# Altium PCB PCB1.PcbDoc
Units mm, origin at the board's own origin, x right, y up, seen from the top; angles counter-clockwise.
Board outline 160 x 100 mm, 4 copper layers (Top Layer, Top inner, Bottom inner, Bottom Layer), stack 1.538 mm thick; 142 components, 85 nets, 480 pads, 109 vias.
Unrouted connection lines stored in the file: 1.
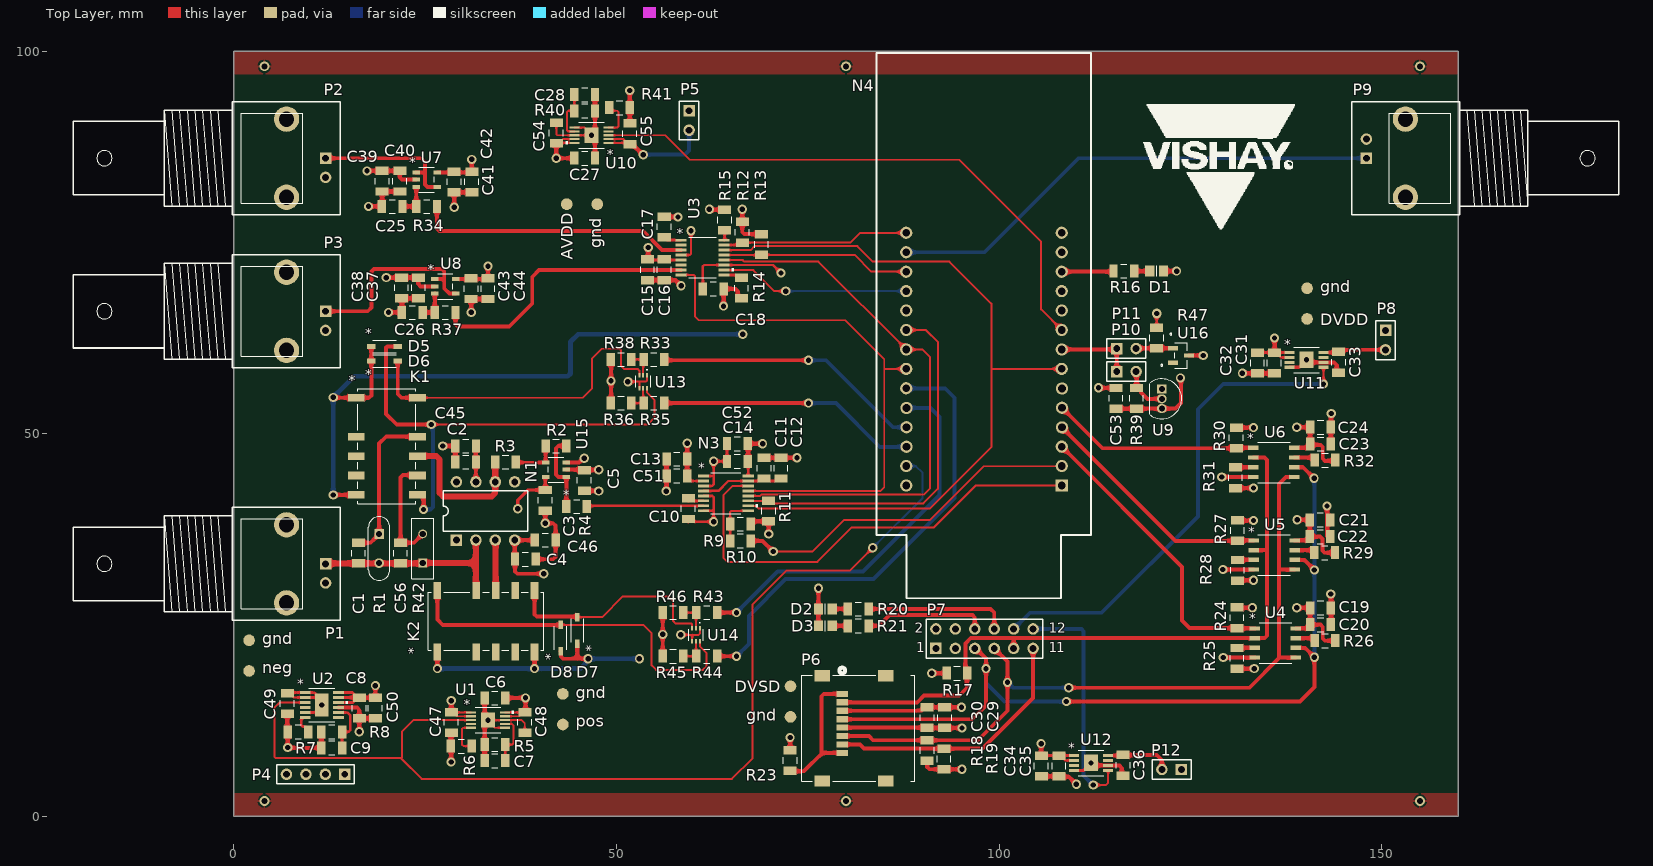
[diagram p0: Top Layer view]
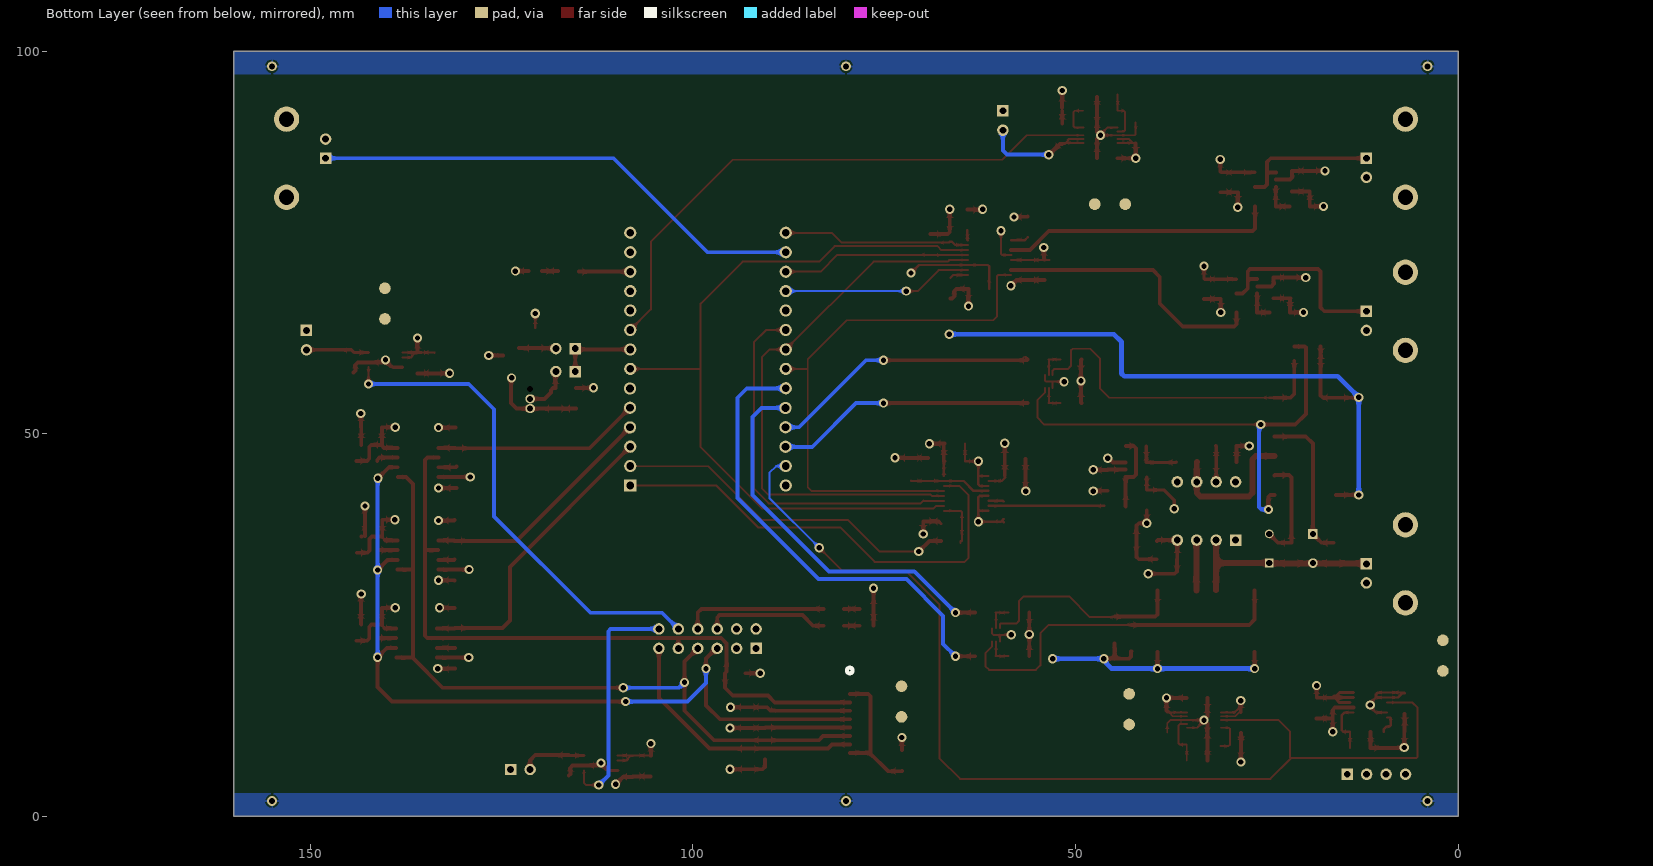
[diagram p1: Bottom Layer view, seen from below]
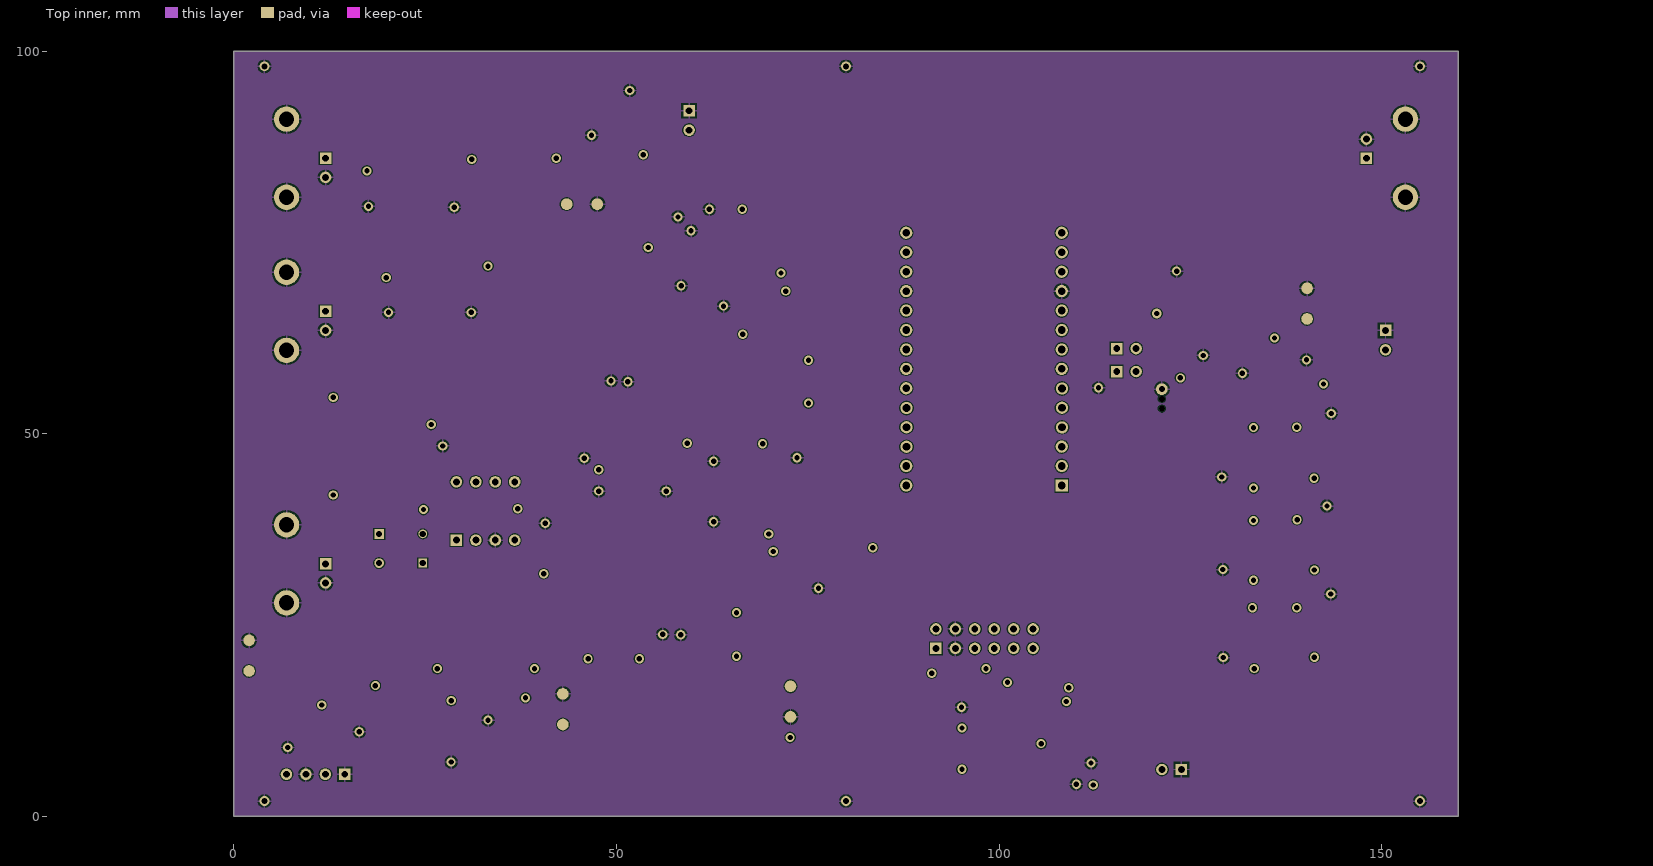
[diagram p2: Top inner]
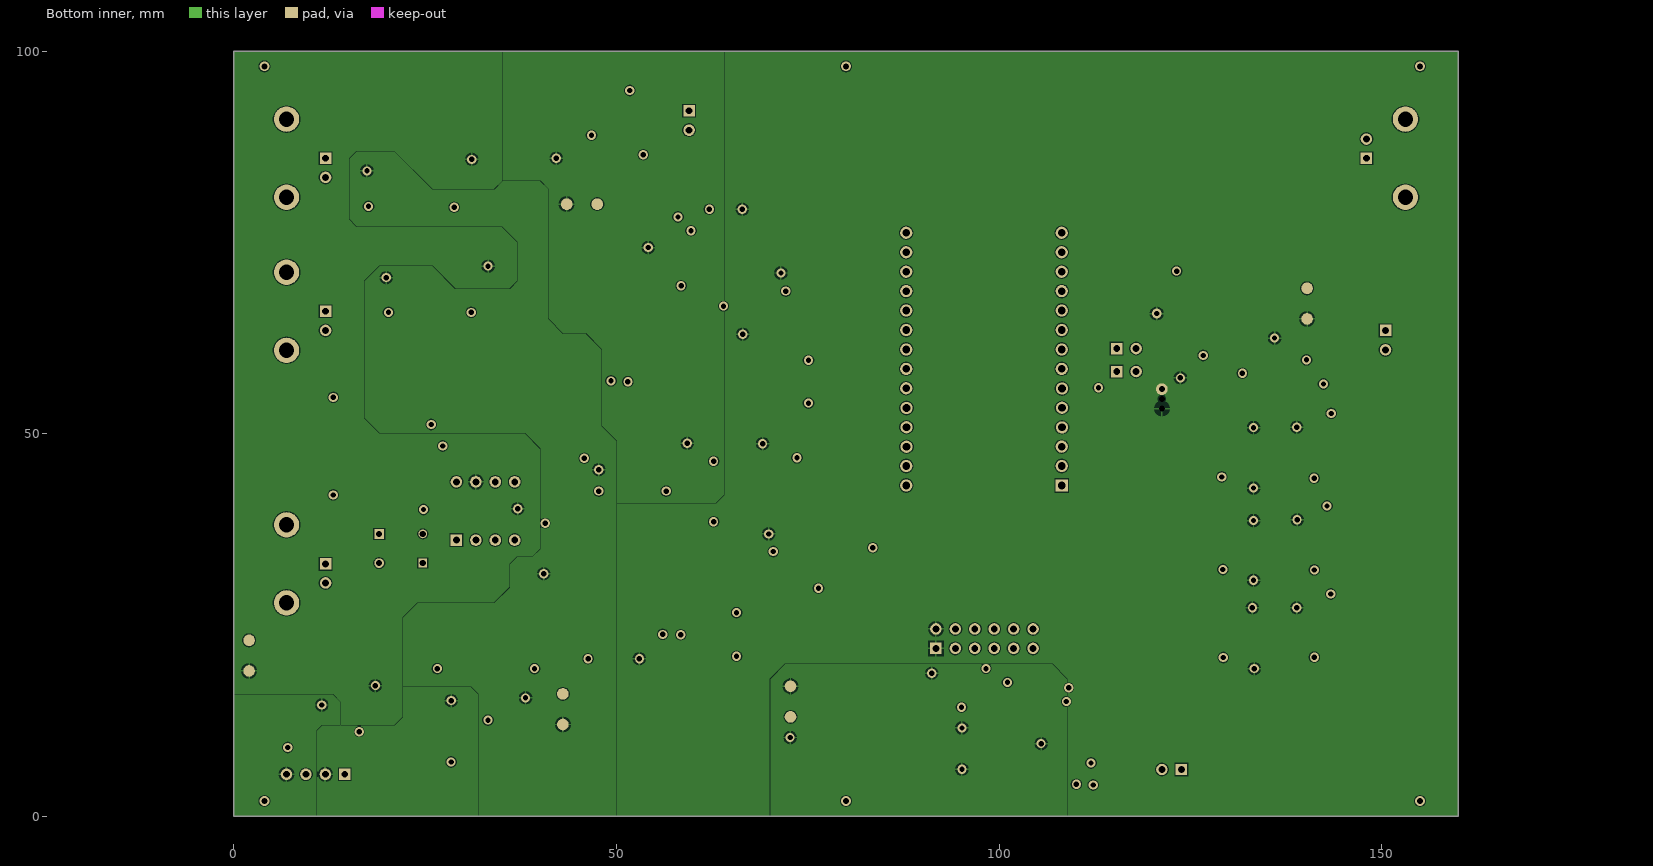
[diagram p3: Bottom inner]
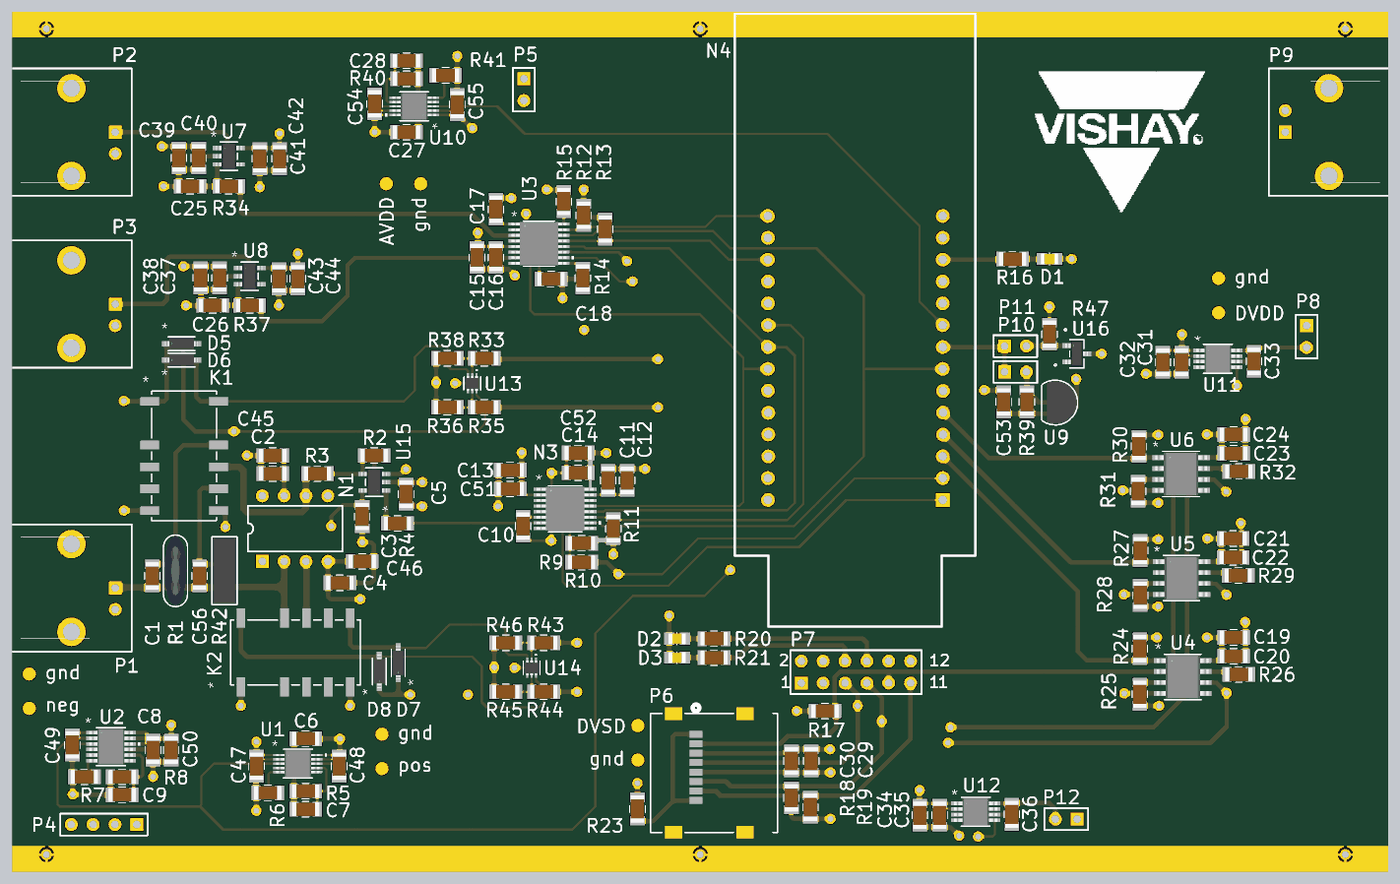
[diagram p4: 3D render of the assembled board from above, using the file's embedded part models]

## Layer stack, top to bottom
Top Solder: solder mask 0.0102, Solder Resist, Dk 3.5
Top Layer: signal copper 0.0356
Dielectric 4: prepreg 0.1524, PP-006, Dk 4.4
Top inner: signal copper 0.035
Dielectric 1: dielectric 1.0922, FR-4, Dk 4.8
Bottom inner: signal copper 0.035
Dielectric 5: prepreg 0.1524, PP-006, Dk 4.4
Bottom Layer: signal copper 0.0356
Bottom Solder: solder mask 0.0102, Solder Resist, Dk 3.5

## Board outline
0,0 160,0 160,100 0,100

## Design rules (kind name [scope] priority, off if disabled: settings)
Clearance [All] p1: gap=0.127 ignorepadtopadclearanceinfootprint=TRUE except(0.025: THPad-THPad)
MinimumSolderMaskSliver THT_21-0248A_Q3-1_MXM [HasFootprint('21-0248A_Q3-1_MXM')] p1: minsoldermaskwidth=0
MinimumSolderMaskSliver [All] p2: minsoldermaskwidth=0.127
PolygonConnect [All] p1: connectstyle=Relief reliefconductorwidth=0.254 reliefentries=4 polygonreliefangle="90 Angle" airgapwidth=0.254
RoutingVias [All] p1: holewidth=0.6 width=1.2 viastyle="Through Hole" minholewidth=0.3 minwidth=0.6 maxholewidth=1 maxwidth=2
SilkToSolderMaskClearance SilkToSolderMaskClearance_1 [HasFootprint('BNC_RA CON')] p1: minsilkscreentomaskgap=0 clearancetoexposedcopper=TRUE
SilkToSolderMaskClearance [IsPad] p2: minsilkscreentomaskgap=0.127 clearancetoexposedcopper=TRUE
SolderMaskExpansion [All] p1: expansion=0.102 istentingtop=FALSE
Width Source [InNet('M_source')] p1: maxlimit=2.54 minlimit=0.254 preferedwidth=0.762
Width Width_1 [All] p2: maxlimit=0.762 minlimit=0.254 preferedwidth=0.762
28 further rules are at their usual default settings.

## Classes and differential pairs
component class U_Cal: R33 R35 R36 R38 R43 R44 R45 R46 U13 U14
component class U_Digital_Psu: C31 C32 C33 C34 C35 C36 U11 U12
component class U_Analog_PSU_5: C27 C28 C54 R40 R41 U10
component class U_Temp_Sensors: C53 P10 P11 R39 R47 U9 U16
component class U_Source_TIA: C1 C2 C3 C4 C5 C45 C46 C56 D5 D6 D7 D8 K1 K2 N1 R1 R2 R3 R4 R42 U15
component class U_PSRAM_SPI: C19 C20 C21 C22 C23 C24 R24 R25 R26 R27 R28 R29 R30 R31 R32 U4 U5 U6
component class U_OPV_psu: C6 C7 C8 C9 C47 C48 C49 C50 R5 R6 R7 R8 U1 U2
component class U_DAC_Buffer_Filter: C25 C26 C37 C38 C39 C40 C41 C42 C43 C44 R34 R37 U7 U8
component class U_CortexM3_dev: C29 C30 D1 D2 D3 N4 P6 R16 R17 R18 R19 R20 R21 R23
component class U_ADC_8681: C10 C11 C12 C13 C14 C51 C52 N3 R9 R10 R11
component class U_AD_5689_DAC: C15 C16 C17 C18 R12 R13 R14 R15 U3
component class Top_Sheet: C55 P1 P2 P3 P4 P5 P8 P9 P12

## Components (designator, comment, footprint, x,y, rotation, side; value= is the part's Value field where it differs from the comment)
C1 "22pF" C1206-KUE 16.3,34.4 r90 top
C2 "100nF" C1206-KUE 30.3,46.3 r0 top
C3 "100nF" C1206-KUE 40.7,41.3 r90 top
C4 "100nF" C1206-KUE 38.1,33.6 r180 top
C5 "100nF" C1206-KUE 45.8,43.9 r90 top
C6 "10uF" C1206-KUE 34.123,15.477 r0 top
C7 "4.7uF" C1206-KUE 34.123,7.277 r0 top
C8 "10uF" C1206-KUE 16.4,14.149 r90 top
C9 "4.7uF" C1206-KUE 12.8,8.949 r0 top
C10 "10uF" C1206-KUE 59.4,40.2 r90 top
C11 "100nF" C1206-KUE 69.3,45.5 r270 top
C12 "10uF" C1206-KUE 71.5,45.5 r270 top
C13 "0.1uF" C1206-KUE 57.9,46.7 r0 top
C14 "0.1uF" C1206-KUE 65.8,46.4 r0 top
C15 "10uF" C1206-KUE 54.05,71.425 r90 top
C16 "0.1uF" C1206-KUE 56.25,71.425 r90 top
C17 "0.1uF" C1206-KUE 56.25,77.025 r270 top
C18 "0.1uF" C1206-KUE 62.65,68.925 r180 top
C19 "1uF" C1206-KUE 142,27.25 r180 top
C20 "100nF" C1206-KUE 142,25.05 r180 top
C21 "1uF" C1206-KUE 141.95,38.75 r180 top
C22 "100nF" C1206-KUE 141.95,36.55 r180 top
C23 "1uF" C1206-KUE 142,48.65 r180 top
C24 "100nF" C1206-KUE 142,50.85 r180 top
C25 "1uF" C1206-KUE 20.7,79.7 r0 top
C26 "1uF" C1206-KUE 23.324,65.85 r0 top
C27 "10uF" C1206-KUE 45.849,86 r180 top
C28 "4.7uF" C1206-KUE 45.849,94.3 r180 top
C29 "100nF" C1206-KUE 92.9,12.9 r270 top
C30 "1uF" C1206-KUE 90.6,12.9 r270 top
C31 "100nF" C1206-KUE 135.972,59.243 r90 top
C32 "10uF" C1206-KUE 133.772,59.243 r90 top
C33 "10uF" C1206-KUE 144.372,59.343 r90 top
C34 "100nF" C1206-KUE 105.523,6.579 r90 top
C35 "10uF" C1206-KUE 107.823,6.579 r90 top
C36 "4.7uF" C1206-KUE 116.223,6.679 r90 top
C37 "100nF" C1206-KUE 24.124,69.05 r90 top
C38 "1uF" C1206-KUE 21.924,69.05 r90 top
C39 "100nF" C1206-KUE 19.4,83 r90 top
C40 "1uF" C1206-KUE 21.7,83 r90 top
C41 "100nF" C1206-KUE 28.8,82.9 r90 top
C42 "1uF" C1206-KUE 31.1,82.9 r90 top
C43 "100nF" C1206-KUE 31.024,68.95 r90 top
C44 "1uF" C1206-KUE 33.224,68.95 r90 top
C45 "10uF" C1206-KUE 30.3,48.4 r0 top
C46 "10uF" C1206-KUE 40.7,36.1 r0 top
C47 "10uF" C1206-KUE 28.423,12.277 r90 top
C48 "100nF" C1206-KUE 38.023,12.277 r90 top
C49 "10uF" C1206-KUE 7,14.749 r90 top
C50 "100nF" C1206-KUE 18.5,14.149 r90 top
C51 "10uF" C1206-KUE 57.9,44.5 r0 top
C52 "10uF" C1206-KUE 65.8,48.7 r0 top
C53 "1uF" C1206-KUE 115.273,54.627 r270 top
C54 "100nF" C1206-KUE 42.149,89.3 r270 top
C55 "100nF" C1206-KUE 51.749,89.2 r270 top
C56 "22pF" C1206-KUE 21.8,34.4 r90 top
D1 "GREEN" 6-0805_N-KUE 120.6,71.25 r0 top
D2 "GREEN" 6-0805_N-KUE 77.3,27.1 r180 top
D3 "RED" 6-0805_N-KUE 77.3,24.9 r180 top
D5 "1N4148W-7" SOD123_DIO 19.7,61.4 r0 top
D6 "1N4148W-7" SOD123_DIO 19.7,59.5 r0 top
D7 "1N4148W-7" SOD123_DIO 44.9,24.3 r90 top
D8 "1N4148W-7" SOD123_DIO 42.7,23.3 r90 top
K1 "G6SK-2F-TR DC3" "RELAY_G6SK-2F DC3_OMR" 24,42 r0 top
K2 "G6SK-2F-TR DC3" "RELAY_G6SK-2F DC3_OMR" 39.3,29.5 r90 top
N1 "LMC6001AIN/NOPB" DIP8 32.9,39.9 r0 top
N3 "ADS8681IPW" PW16_TEX 64.3,42.2 r0 top
N4 "STM32F103" DIP28 112,28.5 r180 top
P1 "BNC" "BNC_RA CON" 12,33 r0 top
P2 "BNC" "BNC_RA CON" 12,86 r0 top
P3 "BNC" "BNC_RA CON" 12,66 r0 top
P4 "Header 4" HDR1X4 14.5,5.5 r180 top
P5 "Header 2" HDR1X2 59.5,92.2 r270 top
P6 "472192001" CONN_47219-2001_MOL 81.6,11.5 r270 top
P7 "Header 6X2" HDR2X6 91.75,21.95 r0 top
P8 "Header 2" HDR1X2 150.5,63.5 r270 top
P9 "BNC" "BNC_RA CON" 148,86 r180 top
P10 "Header 2" HDR1X2 115.373,58.127 r0 top
P11 "Header 2" HDR1X2 115.373,61.127 r0 top
P12 "Header 2" HDR1X2 123.817,6.121 r180 top
R1 "CNS020-10MP" RES_CNS020_VIS 19,36.9 r270 top
R2 "10k" C1206-KUE 42.1,48.4 r180 top
R3 "33k" C1206-KUE 35.5,46.3 r180 top
R4 "10" C1206-KUE 44.8,40.5 r180 top
R5 "78.7k" C1206-KUE 34.123,9.377 r180 top
R6 "0" C1206-KUE 29.723,9.177 r180 top
R7 "0" C1206-KUE 8.4,11.049 r180 top
R8 "78.7k" C1206-KUE 12.8,11.049 r180 top
R9 "10k" C1206-KUE 66.2,38.2 r180 top
R10 "1k" C1206-KUE 66.2,36 r180 top
R11 "4.7k" C1206-KUE 69.9,39.9 r90 top
R12 "4.7k" C1206-KUE 66.45,76.325 r270 top
R13 "4.7k" C1206-KUE 68.95,74.725 r270 top
R14 "10k" C1206-KUE 66.35,69.025 r270 top
R15 "10k" C1206-KUE 64.15,77.925 r90 top
R16 "3.9k" C1206-KUE 116.3,71.25 r0 top
R17 "4.7k" C1206-KUE 94.5,18.7 r0 top
R18 "4.7k" C1206-KUE 90.6,8.6 r90 top
R19 "4.7k" C1206-KUE 92.8,7.5 r90 top
R20 "3.9k" C1206-KUE 81.6,27.1 r180 top
R21 "2.7k" C1206-KUE 81.6,24.9 r180 top
R23 "4.7k" C1206-KUE 72.7,7.3 r90 top
R24 "4.7k" C1206-KUE 131.1,25.95 r270 top
R25 "10k" C1206-KUE 131.1,20.65 r90 top
R26 "10k" C1206-KUE 142.6,22.95 r180 top
R27 "4.7k" C1206-KUE 131.15,37.35 r270 top
R28 "10k" C1206-KUE 131.15,32.15 r90 top
R29 "10k" C1206-KUE 142.55,34.45 r180 top
R30 "4.7k" C1206-KUE 131,49.45 r270 top
R31 "10k" C1206-KUE 130.9,44.25 r90 top
R32 "10k" C1206-KUE 142.6,46.55 r180 top
R33 "1k" C1206-KUE 54.9,59.7 r0 top
R34 "10k" C1206-KUE 25.2,79.7 r180 top
R35 "1k" C1206-KUE 54.9,54 r0 top
R36 "10k" C1206-KUE 50.6,54 r180 top
R37 "10k" C1206-KUE 27.624,65.85 r180 top
R38 "10k" C1206-KUE 50.6,59.7 r180 top
R39 "4.7k" C1206-KUE 117.973,54.627 r90 top
R40 "49.9k" C1206-KUE 45.849,92.2 r0 top
R41 "0" C1206-KUE 50.4,92.6 r0 top
R42 "Y0062100K000T9L" RES_S102K_7P62X2P67_VIS 24.7,33.1 r90 top
R43 "1k" C1206-KUE 61.8,26.625 r0 top
R44 "1k" C1206-KUE 61.8,20.925 r0 top
R45 "10k" C1206-KUE 57.4,20.925 r180 top
R46 "10k" C1206-KUE 57.4,26.625 r180 top
R47 "1k" C1206-KUE 120.6,62.5 r270 top
U1 "LT3042EMSE#TRPBF" 05-08-1664_ADI 33.223,12.577 r0 top
U2 "LT3094EMSE#TRPBF" MSE_05-08-1666_ADI 11.5,14.549 r0 top
U3 "AD5689RBRUZ" RU_16_ADI 61.25,73.025 r0 top
U4 "APS6404L-3SQR-SN" APS6404L-3SQR-SN_APY 136.1,22.65 r0 top
U5 "APS6404L-3SQR-SN" APS6404L-3SQR-SN_APY 135.95,34.15 r0 top
U6 "APS6404L-3SQR-SN" APS6404L-3SQR-SN_APY 135.9,46.25 r0 top
U7 "OPA197IDBVR" DBV5_TEX 25.2,83.2 r0 top
U8 "OPA197IDBVR" DBV5_TEX 27.624,69.25 r0 top
U9 "DS18B20+" 21-0248A_Q3-1_MXM 121.273,55.827 r270 top
U10 "LT3042EMSE#TRPBF" 05-08-1664_ADI 46.749,89 r180 top
U11 "TLV76733DGNR" VSSOP8_DGN_TEX 140.172,59.643 r0 top
U12 "TLV76733DGNR" VSSOP8_DGN_TEX 112.023,6.979 r0 top
U13 "DMC2400UV-7" SON_400UV-7_DIO 53.5,56.8 r270 top
U14 "DMC2400UV-7" SON_400UV-7_DIO 60.4,23.725 r270 top
U15 "OPA197IDBVR" DBV5_TEX 42.1,45.3 r180 top
U16 "DS28E05R+U" 21-0051H_MXM 123.773,60.227 r270 top

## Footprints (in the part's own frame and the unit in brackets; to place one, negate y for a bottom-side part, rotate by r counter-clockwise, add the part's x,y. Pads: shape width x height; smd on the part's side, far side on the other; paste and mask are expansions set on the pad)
05-08-1664_ADI [mil]
  rect 52.28x11 smd paste+0 mask+0: 1(-87.14,39.37) 2(-87.14,19.69) 3(-87.14,0) 4(-87.14,-19.68) 5(-87.14,-39.37) 6(87.14,-39.37) 7(87.14,-19.68) 8(87.14,0) 9(87.14,19.69) 10(87.14,39.37)
  rect 70x78 smd paste+0 mask+0: 11(0,0)
  silkscreen extent -66,-66 133,66, body extent -99,-61 99,61, height 43
6-0805_N-KUE [mm] "Chip Resistor, Body 2.0x1.2mm, IPC Medium Density"
  rect 1.2x1.4 smd: 1(-0.9,0) 2(0.9,0)
  silkscreen extent 0,-0.69 0,0.69, body extent -1,-0.63 1,0.63, height 0.8
21-0051H_MXM [mil]
  rect 22x51 smd paste+0 mask+0: 1(-37.4,-40.5) 2(37.4,-40.5) 3(0,40.5)
  silkscreen extent -115,-57 65,33, body extent -60,-52 60,52, height 44
21-0248A_Q3-1_MXM [mm]
  rect 1.168x1.27 / inner round 1.524 / far side rect 1.168x0 hole 0.8 paste-0.635 mask+0: 1(0,0)
  oval 1.168x1.27 / inner oval 1.524x0 / far side oval 1.168x1.27 hole 0.8 paste-0.635 mask+0: 2(1.27,0) 3(2.54,0)
  silkscreen extent -3.24,-1.59 3.87,2.6, body extent -1.21,-0.95 3.75,2.48, height 4.95
APS6404L-3SQR-SN_APY [mm]
  rect 1.356x0.558 smd paste+0 mask+0: 1(-2.672,1.905) 2(-2.672,0.635) 3(-2.672,-0.635) 4(-2.672,-1.905) 5(2.672,-1.905) 6(2.672,-0.635) 7(2.672,0.635) 8(2.672,1.905)
  silkscreen extent -2.12,-2.63 2.12,2.63, body extent -3,-2.5 3,2.5, height 1.76
"BNC_RA CON" [mm] "Connector; BNC Elbow"
  rect 1.5x1.5 hole 0.9: 1(0,0)
  round 3.3 hole 2: 2(-5.1,-5.1) 2(-5.1,5.1)
  round 1.5 hole 0.9: 2(0,-2.5)
  silkscreen extent -33,-7.4 1.9,7.4
C1206-KUE [mm] "Chip Capacitor, Body 3.2x1.6mm, IPC High Density"
  rect 1.1x1.7 smd: 1(-1.35,0) 2(1.35,0)
  silkscreen extent -0.4,-0.9 0.4,0.9, body extent -1.6,-0.8 1.6,0.8, height 0.95
CONN_47219-2001_MOL [mil]
  rect 32x59 smd paste+0 mask+0: 1(126.18,-82.61) 2(82.87,-82.61) 3(39.57,-82.61) 4(-3.74,-82.61) 5(-47.05,-82.61) 6(-90.35,-82.61) 7(-133.66,-82.61) 8(-176.97,-82.61)
  rect 57x79 smd paste-39.5 mask-39.5: G1(270.67,-184.97) G2(270.67,141.8) G3(-270.67,141.8) G4(-270.67,-184.97)
  silkscreen extent -312,-291 273,290
DBV5_TEX [mil]
  rect 38.5x20 smd paste+0 mask+0: 1(-53.75,37.4) 2(-53.75,0) 3(-53.75,-37.4) 4(53.75,-37.4) 5(53.75,37.4)
  silkscreen extent -40,-65 39,65, body extent -59,-60 59,60, height 57
DIP8 [mm] "DIP; 8 Leads; Row Spacing 7.62 mm; Pitch 2.54 mm"
  rect 1.5x1.5 hole 0.9: 1(-3.81,-3.81)
  round 1.5 hole 0.9: 2(-1.27,-3.81) 3(1.27,-3.81) 4(3.81,-3.81) 5(3.81,3.81) 6(1.27,3.81) 7(-1.27,3.81) 8(-3.81,3.81)
  silkscreen extent -5.5,-2.65 5.5,2.65
DIP28 [mm]
  round 1.6 hole 1: 1(24.13,-47.752) 2(24.13,-45.212) 3(24.13,-42.672) 4(24.13,-40.132) 5(24.13,-37.592) 6(24.13,-35.052) 7(24.13,-32.512) 8(24.13,-29.972) 9(24.13,-27.432) 10(24.092,-24.868) 11(24.092,-22.349) 12(24.092,-19.788) 13(24.13,-17.272) 14(24.13,-14.732) 15(3.81,-47.752) 16(3.81,-45.212) 17(3.81,-42.672) 18(3.81,-40.132) 19(3.81,-37.592) 20(3.81,-35.052) 21(3.81,-32.512) 22(3.81,-29.972) 23(3.772,-27.408) 24(3.772,-24.889) 25(3.772,-22.328) 26(3.81,-19.812) 27(3.81,-17.272)
  rect 1.6x1.6 hole 1: 28(3.81,-14.732)
  silkscreen extent 0,-71.26 28,0
HDR1X2 [mm] "Connector; Header; 2 Position"
  rect 1.5x1.5 hole 0.9: 1(0,0)
  round 1.5 hole 0.9: 2(2.54,0)
  silkscreen extent -1.27,-1.27 3.81,1.27
HDR1X4 [mm] "Connector; Header; 4 Position"
  rect 1.5x1.5 hole 0.9: 1(0,0)
  round 1.5 hole 0.9: 2(2.54,0) 3(5.08,0) 4(7.62,0)
  silkscreen extent -1.27,-1.27 8.89,1.27
HDR2X6 [mm] "Connector; Header; 6x2 Position"
  rect 1.5x1.5 hole 0.9: 1(0,0)
  round 1.5 hole 0.9: 2(0,2.54) 3(2.54,0) 4(2.54,2.54) 5(5.08,0) 6(5.08,2.54) 7(7.62,0) 8(7.62,2.54) 9(10.16,0) 10(10.16,2.54) 11(12.7,0) 12(12.7,2.54)
  silkscreen extent -1.27,-1.27 13.97,3.81
MSE_05-08-1666_ADI [mil]
  rect 54.56x16.97 smd paste+0 mask+0: 1(-86,63.98) 2(-86,38.39) 3(-86,12.8) 4(-86,-12.8) 5(-86,-38.39) 6(-86,-63.98) 7(86,-63.98) 8(86,-38.39) 9(86,-12.8) 10(86,12.8) 11(86,38.39) 12(86,63.98)
  rect 69x116 smd paste-57.5 mask+0: 13(0,0)
  silkscreen extent -66,-87 133,86, body extent -99,-81 99,81, height 43
PW16_TEX [mil]
  rect 58x14 smd paste+0 mask+0: 1(-115,89.57) 2(-115,63.98) 3(-115,38.39) 4(-115,12.8) 5(-115,-12.79) 6(-115,-38.39) 7(-115,-63.98) 8(-115,-89.57) 9(115,-89.57) 10(115,-63.98) 11(115,-38.39) 12(115,-12.8) 13(115,12.8) 14(115,38.39) 15(115,63.98) 16(115,89.57)
  silkscreen extent -76,-106 164,105, body extent -130,-101 130,101, height 47
"RELAY_G6SK-2F DC3_OMR" [mil]
  rect 87x39 smd paste+0 mask+0: 1(-314.96,500) 3(-314.96,300) 4(-314.96,200) 5(-314.96,100) 6(-314.96,0) 7(0,0) 8(0,100) 9(0,200) 10(0,300) 12(0,500)
  silkscreen extent -306,-46 -9,546
RES_CNS020_VIS [mm]
  rect 1.27x1.27 hole 0.8 paste-0.635 mask+0: 1(0,0)
  round 1.27 hole 0.8 paste-0.635 mask+0: 2(3.81,0)
  silkscreen extent -2.26,-1.4 6.07,1.4, body extent -2.13,-1.27 5.94,1.27, height 6.6
RES_S102K_7P62X2P67_VIS [mil]
  rect 45x45 hole 31.5 paste-22.5 mask+0: 1(0,0)
  round 45 hole 31.5 paste-22.5 mask+0: 2(150,0)
  silkscreen extent -80,-57 230,58, body extent -75,-53 225,53, height 336
RU_16_ADI [mm]
  rect 1.461x0.351 smd paste+0 mask+0: 1(-2.825,2.275) 2(-2.825,1.625) 3(-2.825,0.975) 4(-2.825,0.325) 5(-2.825,-0.325) 6(-2.825,-0.975) 7(-2.825,-1.625) 8(-2.825,-2.275) 9(2.825,-2.275) 10(2.825,-1.625) 11(2.825,-0.975) 12(2.825,-0.325) 13(2.825,0.325) 14(2.825,0.975) 15(2.825,1.625) 16(2.825,2.275)
  silkscreen extent -1.81,-2.63 4.06,2.63, body extent -3.2,-2.5 3.2,2.5, height 1.2
SOD123_DIO [mm]
  rect 1.111x0.601 smd paste+0 mask+0: 1(-1.725,0) 2(1.725,0)
  silkscreen extent -1.55,-0.8 1.55,0.8, body extent -1.92,-0.67 1.92,0.67, height 0.81
SON_400UV-7_DIO [mil]
  rect 24x10 smd paste+0 mask+0: 1(-33.5,19.69) 2(-33.5,0) 3(-33.5,-19.68) 4(33.5,-19.68) 5(33.5,0) 6(33.5,19.69)
  silkscreen extent -62,-39 29,38, body extent -34,-34 34,34, height 24
VSSOP8_DGN_TEX [mil]
  rect 52.5x17 smd paste+0 mask+0: 1(-87.25,38.38) 2(-87.25,12.79) 3(-87.25,-12.8) 4(-87.25,-38.39) 5(87.25,-38.39) 6(87.25,-12.8) 7(87.25,12.79) 8(87.25,38.38)
  rect 73x85 smd paste+0 mask+0: EPAD(0,0)
  silkscreen extent -66,-66 66,66, body extent -99,-61 99,61, height 43

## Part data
C1 C2 C3 C4 C5 C6 C7 C8 C9 C10 C11 C12 C13 C14 C15 C16 C17 C18 C19 C20 C21 C22 C23 C24 C25 C26 C27 C28 C29 C30 C31 C32 C33 C34 C35 C36 C37 C38 C39 C40 C41 C42 C43 C44 C45 C46 C47 C48 C49 C50 C51 C52 C53 C54 C55 C56: library part Capacitor, "Capacitor", Manufacturer=Kemet
D1 D2 D3: library part LED0, "Typical INFRARED GaAs LED"
D5 D6 D7 D8 U13 U14: "Description", Manufacturer_Name="Diodes Inc"
K1 K2: "Description", Manufacturer_Name=Omron
N1: library part LMC6001AINNOPB, "Ultra-Low Input Current Amplifier 8-PDIP -40 to 85", Manufacturer=NationalSemiconductor, Manufacturer_Name="Texas Instruments", PartNumber=LMC6001AIN
N3: "16-bit, 1MSPS 1-ch SAR ADC with programmable (Â±12V, Â±10V, Â±6V, Â±5V, Â±2.5V) input ranges on 5V supply 16-TSSOP -40 to 125", Manufacturer_Name="Texas Instruments"
P1 P2 P3 P9: "BNC Elbow Connector"
P4: "Header, 4-Pin"
P5 P8 P10 P11 P12: "Header, 2-Pin"
P6: "1.10mm Pitch microSD Card Connector, Hinge Type, Lead-Free", Manufacturer_Name="Molex Connector Corporation"
P7: "Header, 6-Pin, Dual row"
R1: library part CNS020-10KP, "CNS 020 10K 0,02% e2", Manufacturer_Name=Vishay
R2 R3 R4 R5 R6 R7 R8 R9 R10 R11 R12 R13 R14 R15 R16 R17 R18 R19 R20 R21 R23 R24 R25 R26 R27 R28 R29 R30 R31 R32 R33 R34 R35 R36 R37 R38 R39 R40 R41 R43 R44 R45 R46 R47: library part ResistorSMD, "Resistor SMD", Manufacturer=AVX
R42: "No Description Available", Manufacturer_Name=Vishay
U1 U10: library part LT3042EMSETRPBF, "20V, 200mA, Ultralow Noise, Ultrahigh PSRR RF Linear Regulator", Manufacturer_Name="Analog Devices Inc"
U2: library part LT3094EMSETRPBF, "âˆ’20V, 500mA, Ultralow Noise, Ultrahigh PSRR Negative Linear Regulator", Manufacturer_Name="Analog Devices Inc"
U3: "Dual, 16-Bit nanoDAC+ with 2 ppm/Â°C Reference, SPI Interface", Manufacturer_Name="Analog Devices Inc"
U4 U5 U6: "Description", Manufacturer_Name="AP Memory"
U7 U8 U15: "Single, 36-V, precision, rail-to-rail input output, low offset voltage op amp 5-SOT-23 -40 to 125", Manufacturer_Name="Texas Instruments"
U9: "Programmable Resolution 1-Wire Digital Thermometer", Manufacturer_Name="Analog Devices Inc"
U11 U12: "Adjustable- and fixed-output, 1-A, 16-V, positive-voltage low-dropout (LDO) linear regulator 8-HVSSOP -40 to 125", Manufacturer_Name="Texas Instruments"
U16: "1-Wire EEPROM", Manufacturer_Name="Analog Devices Inc"

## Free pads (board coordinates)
  round 1.524 all layers, no hole: 16(2,19) 16(2,23) 16(43,12) 16(43,16) 16(43.5,80) 16(47.5,80) 16(72.75,13) 16(72.75,17) 16(140.25,65) 16(140.25,69)

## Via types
v1: diameter 1.2, hole 0.7, Top Layer to Bottom Layer, 102 vias
v2: diameter 1.27, hole 0.8, Top Layer to Bottom Layer, 6 vias
v3: diameter 1.27, hole 0.7, Top Layer to Bottom Layer, 1 vias

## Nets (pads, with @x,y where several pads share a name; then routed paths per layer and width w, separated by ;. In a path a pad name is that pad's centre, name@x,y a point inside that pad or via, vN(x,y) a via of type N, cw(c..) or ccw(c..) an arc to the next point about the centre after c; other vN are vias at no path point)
AVDD: C13.2 C15.2 C16.2 C27.2 C51.2 C54.2 N3.2 pad.16@43.5,80 U3.5 U10.9 U10.10 | length 22.4
  Top Layer w0.254: C54.2@42.199,88 C54.2@42.499,88 ; U10.10 C54.2@42.499,88 ; U10.9 42.999,88.5 C54.2@42.499,88
  Top Layer w0.305: C15.2@53.425,72.7 C15.2@54.125,72.7 ; C15.2 C15.2@54.125,72.7 ; U3.5 C15.2@54.125,72.7 ; C51.2 59.25,44.223 59.648,43.825 N3.2
  Top Layer w0.508: C54.2 v1(42.149,86) C27.2 ; C15.2 54.15,72.875 v1(54.15,74.325) ; C51.2 C13.2 v1(59.25,48.75)
damper_out: R2.1 R4.2 U15.1 | length 10.3
  Top Layer w0.508: R4.2 43.465,40.515 U15.1 42.398,44.35 42.1,44.648 42.1,48.102 42.398,48.4 R2.1
DVDD: C14.2 C18.2 C19.2 C20.2 C21.2 C22.2 C23.2 C24.2 C31.2 C32.2 C52.2 C53.2 D5.1 D6.1 D7.1 D8.1 K1.1 K1.6 K2.1 K2.6 N3.16 P7.1 P7.2 pad.16@140.25,65 R9.1 R11.1 R12.1 R13.1 R24.1 R25.1 R26.1 R27.1 R28.1 R29.1 R30.1 R31.1 R32.1 R39.1 R47.1 U3.11 U4.8 U5.8 U6.8 U9.3 U11.1 U11.2 | length 223.4
  Top Layer w0.305: C18.2 61.3,71.871 61.479,72.05 U3.11 70.45,72.05 v1(71.5,71) ; C52.2 C52.2@67.221,48.629 ; N3.16 C14.2@67.221,46.329 ; R9.1 R9.1@67.9,38.55 ; R47.1 v3(120.6,65.7) ; R24.1 R24.1@131.15,27.25 ; C32.2 133.797,60.618 136.122,60.618 U11.1 ; C31.2 136.272,60.593 136.669,60.196 136.669,60.147 136.848,59.968 U11.2 ; C22.2@140.202,36.055 140.6,36.453 C22.2 ; C20.2@140.252,24.555 140.65,24.953 C20.2
  Top Layer w0.508: v1(13,42) K1.6 ; v1(13,54.75) 13.05,54.7 K1.1 17.677,54.7 17.975,54.998 D6.1 D5.1 ; v1(26.6,19.3) K2.1 ; v1(39.3,19.3) K2.6 ; D8.1 42.746,21.529 42.746,20.898 43.044,20.6 44.9,20.6 ; D7.1 44.9,20.6 ; v1(46.3,20.6) 44.9,20.6 ; v1(66.45,79.325) R12.1 66.45,76.325 66.7,76.075 R13.1 ; C14.2 C14.2@67.221,46.329 ; C52.2 v1(69.1,48.7) ; C14.2@67.221,46.4 C52.2@67.221,48.629 ; R9.1@67.9,38.55 R11.1 v1(69.9,36.9) ; C53.2 R39.1 121.263,53.277 U9.3 123.033,53.287 123.773,54.027 v1@123.773,57.427 ; R31.1 v1(133.25,42.9) ; R30.1 v1(133.25,50.8) ; R25.1 v1(133.35,19.3) ; R24.1@131.15,27.25 v1(133.1,27.25) ; R28.1 131.2,30.85 v1(133.25,30.85) ; R27.1 131.2,38.65 v1(133.25,38.65) ; v1(136,62.5) 136,60.74 C31.2@136.122,60.618 ; U6.8 140.354,48.155 140.65,48.451 C23.2@140.65,48.55 ; U5.8 C22.2@140.202,36.055 ; U4.8 C20.2@140.252,24.555 ; v1(138.9,27.25) C19.2 C20.2 142,25.05 142.3,24.75 142.3,23.248 142.598,22.95 R26.1 ; v1(138.9,50.85) C24.2 C23.2 C23.2@140.65,48.55 ; v1(138.95,38.75) C21.2 C22.2 141.952,36.55 142.25,36.252 142.25,34.748 142.548,34.45 R29.1 ; R32.1@143.95,46.45 142.598,46.45 142.3,46.748 142.3,48.252 142.002,48.55 C23.2@140.65,48.55
  Bottom Layer w0.635: v1(13,42) v1(13,54.75) 15.75,57.5 43.628,57.5 44,57.872 44,62 45,63 v1(66.5,63) ; v1(26.6,19.3) v1(39.3,19.3) 45.3,19.3 45.983,19.983 45.983,20.111 46.3,20.428 v1(46.3,20.6) v1(53,20.6)
  other v1: 123.7,57.3
DVDD_SD: C29.2 C30.2 C34.2 C35.2 P6.4 pad.16@72.75,17 R17.1 R18.1 R19.1 R23.2 U12.1 U12.2 | length 33.1
  Top Layer w0.305: C34.2 105.548,7.953 U12.1 ; C35.2 108.123,7.929 108.52,7.531 108.52,7.482 108.699,7.303 U12.2
  Top Layer w0.508: R23.2 v1(72.7,10.3) ; P6.4 C30.2@90.555,11.595 ; R18.1@90.6,7.45 90.6,6.448 90.898,6.15 R19.1 v1(95.15,6.15) ; C30.2 C29.2 v1(95.15,11.55) v1@95.2,11.6 ; v1(91.2,18.7) R17.1 ; v1(105.5,9.5) 105.5,7.951 C34.2
GND: C2.1 C3.1 C4.1 C5.1 C6.1 C7.1 C8.1 C9.1 C10.1 C11.1 C12.1 C13.1 C14.1 C15.1 C16.1 C17.1 C18.1 C19.1 C20.1 C21.1 C22.1 C23.1 C24.1 C25.1 C26.1 C27.1 C28.1 C29.1 C30.1 C31.1 C32.1 C33.1 C34.1 C35.1 C36.1 C37.1 C38.1 C39.1 C40.1 C41.1 C42.1 C43.1 C44.1 C45.1 C46.2 C47.1 C48.1 C49.1 C50.1 C51.1 C52.1 C53.1 C54.1 C55.1 D1.2 D2.2 D3.2 K2.9 N1.3 N3.1 N3.3 N3.5 N3.8 N4.18 P1.2 P2.2 P3.2 P4.1 P4.3 P5.1 P6.6 P7.3 P7.4 P8.1 P9.2 P12.1 pad.16@2,23 pad.16@43,16 pad.16@47.5,80 pad.16@72.75,13 pad.16@140.25,69 R5.2 R6.2 R7.2 R8.2 R14.2 R15.2 R36.2 R38.2 R40.2 R41.2 R45.2 R46.2 U1.6 U1.8 U1.11 U2.9 U3.4 U4.4 U5.4 U6.4 U9.1 U10.6 U10.8 U10.11 U11.4 U11.6 U11.EPAD U12.4 U12.6 U12.EPAD U13.1 U13.4 U14.1 U14.4 U15.3 U16.3 | length 247.5
  Top Layer w0.254: U1.11@33.223,12.475 33.985,11.713 33.997,11.713 34.134,11.577 U1.6 ; v1(33.223,12.577) U1.8 37.623,12.577 38.023,12.177 C48.1 ; C54.1 42.149,89.149 42.298,89 U10.8 v1(46.749,89) ; U10.6 45.851,90 U10.11@46.749,89.102 ; v1(51.5,56.8) 53.851,56.8 54,56.949 U13.1 ; U13.4 53,56.651 ; v1(58.4,23.725) 59.9,23.725 ; U14.4 59.9,23.725 ; U14.1 60.9,23.874 60.751,23.725 59.9,23.725
  Top Layer w0.305: U3.4 59.571,73.35 59.75,73.529 v1(59.75,76.525) ; C10.1@59.4,38.45 C10.1@59.45,38.5 ; C10.1 59.75,38.5 v1(62.7,38.5) 62.7,40.104 ; N3.8 62.521,39.925 62.7,40.104 ; N3.5 62.521,41.875 62.7,41.696 62.7,40.104 ; N3.3 62.521,43.175 62.7,43.354 v1(62.7,46.4) C14.1 C52.1 ; N3.1 62.521,44.475
  Top Layer w0.432: U12.4 111.048,6.004 v1(112.023,6.979) ; U12.EPAD@111.312,6.115 U12.EPAD@112.023,6.826 ; U11.4 139.197,58.668 139.346,58.818 U11.EPAD@139.499,58.818
  Top Layer w0.508: C49.1 7,11.099 R7.2 v1(7.05,8.999) 7.1,8.949 C9.1 R8.2 ; U2.9 16.102,14.224 16.4,13.926 C8.1 ; v1(16.4,11.049) C8.1 ; v1(17.6,79.7) C25.1 19.4,79.75 C39.1 C40.1 ; C50.1 C8.1 ; v1(20.224,65.85) C26.1 21.974,67.65 C38.1 C37.1 ; v1(27.3,48.4) C45.1 C2.1 ; v1(28.4,7.1) 28.398,7.102 28.398,9.152 R6.2 28.373,10.877 C47.1 ; v1(28.8,79.6) C41.1 C42.1 ; v1(31.024,65.85) C43.1 C44.1 ; C7.1 R5.2 U1.11@32.773,12.127 ; U1.11@32.773,13.027 C6.1 ; N1.3 N1.3@34.22,36.04 ; C4.1 41.752,33.6 42.05,33.898 C46.2 42.05,38.002 41.752,38.3 v1(40.7,38.3) C3.1 ; U15.3 45.121,46.25 45.671,46.8 v1(45.8,46.8) ; C5.1 45.803,42.547 47.653,42.547 v1(47.7,42.5) ; v1(46.749,89) 47.199,88.55 C27.1 ; U10.11@46.8,89.051 47.199,89.45 R40.2 C28.1@47.199,94 ; R36.2 49.3,54.05 v1(49.3,56.9) 49.3,59.65 R38.2 ; C55.1 R41.2@51.749,92.15 ; R41.2 v1(51.751,94.849) ; C15.1 C16.1 57.7,70.075 v1(58.45,69.325) ; R45.2 v1(56.05,23.775) R46.2 ; C17.1 56.275,78.35 58.025,78.35 v1(58.05,78.325) ; v1(56.5,42.5) 56.55,42.55 C51.1 C13.1 ; v1(62.15,79.325) 62.2,79.275 R15.2 ; v1(64,66.675) C18.1 65.543,68.925 65.841,68.627 65.841,67.971 66.137,67.675 R14.2 ; C11.1 C12.1 v1(73.6,46.85) ; D3.2 D2.2 v1(76.4,29.8) ; P6.6 89.845,13.795 90.3,14.25 C30.1 C29.1 v1(95.1,14.25) ; C34.1 C35.1 ; C35.1@107.823,5.206 107.866,5.163 109.137,5.163 v1(110.1,4.2) ; U12.EPAD@112.023,6.826 v1(112.023,6.979) 112.348,6.653 U12.6 115.725,6.653 116.023,6.356 116.023,5.529 C36.1 ; v1(113,56) 113.023,55.977 C53.1 ; D1.2 v1(123.2,71.25) ; U16.3 v1(126.673,60.227) ; v1(129.1,44.35) 129.105,44.345 U6.4 ; v1(129.25,32.25) 129.255,32.245 U5.4 ; v1(129.3,20.75) 129.305,20.745 U4.4 ; v1(131.8,57.9) 131.807,57.893 C31.1 ; U11.EPAD@139.499,58.818 140.172,59.491 v1(140.172,59.643) 140.497,59.318 U11.6 143.797,59.318 144.107,59.008 144.107,58.258 C33.1 ; C22.1@142.85,36.6 v1(142.85,40.55) ; C22.1 C22.1@143.35,36.6 ; C20.1 143.4,25.1 v1@143.4,29.05 ; C19.1 C19.1@143.375,27.275 ; C23.1@143.35,48.55 C23.1 C24.1 143.375,50.875 143.375,52.625 v1(143.4,52.65)
  Top Layer w0.762: K2.9 N1.3@34.22,36.04
  other v1: 143.35,29.05
  other v2: 4,2 80,2 155,2 4,98 80,98 155,98
M_source: C1.1 C56.1 K2.10 N1.2 P1.1 R1.2 R42.1 | length 26.3
  Top Layer w0.508: R42.1@24.65,33.05 R42.1 ; K2.10@31.58,29.5 K2.10@31.63,29.55
  Top Layer w0.762: P1.1 12.05,33.05 C1.1 C56.1 R42.1@24.65,33.05 ; R42.1 31.63,33.1 ; K2.10@31.63,29.55 31.63,33.1 ; N1.2 31.63,33.1
neg_out: C2.2 C3.2 C8.2 C41.2 C42.2 C43.2 C44.2 C45.2 C50.2 N1.7 pad.16@2,19 U2.10 U2.11 U2.12 U7.5 U8.5 U15.5 | length 35.9
  Top Layer w0.432: U2.11 C8.2@16.075,15.524 ; U2.12 15.513,16.174 15.766,15.921 15.766,15.833 15.925,15.674 16.225,15.674 16.375,15.524 C8.2 ; U2.10@14.161,14.874 15.513,14.874 15.766,15.127 15.766,15.165 16.1,15.499 C8.2@16.25,15.499 ; C8.2@16.225,15.524 C8.2@16.25,15.499 ; v1(18.5,17.083) C50.2 C8.2 ; U7.5 31,84.15 C42.2 v1(31.1,85.848) ; U8.5 33.124,70.2 C44.2 v1(33.224,71.898) ; N1.7 31.63,48.38 C45.2 C45.2@31.675,48.425 ; v1(37.1,40.2) 37.1,41.297 38.453,42.65 C3.2 40.7,44.315 U15.5 ; C8.2@16.25,15.499 C8.2
  Top Layer w0.508: C8.2@15.925,15.674 16.075,15.524 16.225,15.524 C8.2@16.375,15.524
NetC1_2: C1.2 K1.10 R1.1 | length 20.4
  Top Layer w0.508: C1.2 17.85,35.75 R1.1 19,48.7 19.92,49.62 K1.10
NetC7_2: C7.2 R5.1 U1.7 | length 6.7
  Top Layer w0.254: U1.7 36.323,12.077 36.523,11.877 36.523,9.526 36.374,9.377 R5.1 C7.2
NetC9_2: C9.2 R8.1 U2.8 | length 6.9
  Top Layer w0.305: U2.8 14.875,13.574 15.2,13.249 15.2,11.227 15.021,11.049 R8.1 C9.2
NetC17_2: C17.2 U3.1 | length 2.3
  Top Layer w0.305: C17.2 56.625,75.3 U3.1
NetC25_2: C25.2 R34.2 U7.3 | length 4.4
  Top Layer w0.508: C25.2 R34.2 23.85,82.25 U7.3
NetC26_2: C26.2 R37.2 U8.3 | length 4.1
  Top Layer w0.508: C26.2 R37.2 26.274,68.3 U8.3
NetC28_2: C28.2 R40.1 U10.7 | length 6.6
  Top Layer w0.254: C28.2 R40.1 43.698,92.2 43.549,92.051 43.549,89.649 43.698,89.5 U10.7
NetC33_2: C33.2 P8.2 U11.8 | length 8.3
  Top Layer w0.432: U11.8 144.297,60.618 C33.2 144.638,60.96 P8.2
NetC36_2: C36.2 P12.2 U12.8 | length 8.6
  Top Layer w0.432: U12.8 116.148,7.953 C36.2
  Top Layer w0.508: C36.2 116.251,8 120.6,8 121.277,7.323 P12.2
NetC47_2: C47.2 P4.2 U1.1 U1.2 | length 6.6
  Top Layer w0.254: v1(28.412,15.123) v1@28.423,15.111 ; C47.2@28.584,13.627 29.134,13.077 U1.2 ; C47.2@28.723,14.027 29.173,13.577 U1.1
  Top Layer w0.508: C47.2 v1@28.423,15.111
NetC49_2: C49.2 P4.4 U2.1 U2.2 U2.5 U2.13 | length 11.8
  Top Layer w0.305: U2.5 10.776,13.574 U2.13@11.5,14.298 ; U2.13@11.5,14.8 U2.13@10.776,15.524 ; U2.13@10.776,15.524 10.776,15.873 10.475,16.174 U2.1 7.075,16.174 C49.2 7.3,16.099 7.875,15.524 U2.2 U2.13@10.776,15.524
  other v1: 11.5,14.549
NetC55_2: C55.2 P5.2 U10.1 U10.2 | length 16.6
  Top Layer w0.254: U10.1 C55.2@51.299,88 ; U10.2 50.878,88.5 51.026,88.351 51.026,88.273 C55.2@51.299,88 ; C55.2@51.449,87.85 C55.2@51.299,88 ; C55.2@51.599,88 C55.2@51.299,88
  Top Layer w0.508: C55.2 52.049,87.85 53.439,86.46 v1(53.511,86.46)
  Bottom Layer w0.508: v1(53.511,86.46) 58.96,86.46 59.5,87 P5.2
NetC56_2: C56.2 K1.8 R42.2 | length 14.3
  Top Layer w0.508: K1.8 23.94,44.6 22.098,44.6 21.8,44.302 C56.2 23.54,35.75 R42.2
NetD1_1: D1.1 R16.2 | length 2.1
  Top Layer w0.508: R16.2 D1.1
NetD2_1: D2.1 R20.2 | length 2
  Top Layer w0.508: D2.1 R20.2
NetD3_1: D3.1 R21.2 | length 2
  Top Layer w0.508: D3.1 R21.2
NetD5_2: D5.2 K1.7 U13.6 | length 65.3
  Top Layer w0.254: v1(25.8,51.2) 54.075,51.2 55,52.125 55,54.351 54,55.351 U13.6
  Top Layer w0.508: D5.2 20.049,61.4 19.9,61.251 19.9,52.6 21.3,51.2 v1(25.8,51.2) ; K1.7 24.559,42 24.8,41.759 v1(24.8,40.1)
  Bottom Layer w0.508: v1(24.8,40.1) 25.728,40.1 26.026,40.398 26.026,50.787 25.8,51.013 v1(25.8,51.2)
NetD6_2: D6.2 K1.12 U13.3 | length 44
  Top Layer w0.254: K1.12 45.6,54.7 46.8,55.9 46.8,59.8 48.1,61.1 50.4,61.1 50.6,60.9 50.6,58.851 51,58.451 52.8,58.451 53,58.251 U13.3
  Top Layer w0.508: D6.2 21.425,55.175 21.9,54.7 K1.12
NetD7_2: D7.2 K2.7 U14.3 | length 28.5
  Top Layer w0.254: D7.2 48.125,26.025 50.85,28.75 56.775,28.75 57.4,28.125 57.4,25.525 57.7,25.225 59.751,25.225 59.9,25.077 U14.3
  Top Layer w0.508: K2.7 39.3,26.398 39.598,26.1 D7.2@44.854,26.1
NetD8_2: D8.2 K2.12 U14.6 | length 48
  Top Layer w0.254: D8.2@42.675,25 D8.2 53.475,25.025 54.6,23.9 54.6,19.725 55.2,19.125 61.3,19.125 61.8,19.625 61.8,21.335 61.105,22.029 61.096,22.029 60.9,22.225 U14.6
  Top Layer w0.508: K2.12 26.6,25.7 27.3,25 D8.2@42.675,25
NetN3_7: N3.7 R4.1 | length 15.2
  Top Layer w0.305: R4.1@46.225,40.575 48.875,40.575 N3.7
NetN3_9: N3.9 R9.2 R10.2 | length 6.5
  Top Layer w0.254: R10.2 R9.2 64.85,39.75 65.025,39.925 N3.9 ; R10.2@65.05,35.7 R10.2@65.05,36
NetN3_11: N3.11 N4.6 R11.2 | length 49.7
  Top Layer w0.254: N3.11 69.875,41.225 R11.2 70.25,40.9 90.1,40.9 92,42.8 92,62 90.448,63.552 N4.6
NetN3_14: N3.14 N4.28 | length 60.5
  Top Layer w0.254: N3.14 65.175,43.175 64,42 64,33.75 64.5,33.25 76.25,33.25 80.75,37.75 91.5,37.75 96.982,43.232 N4.28
NetN4_1: N4.1 R12.2 U3.15 | length 24.5
  Top Layer w0.254: R12.2 80.576,74.975 81.853,76.252 N4.1
  Top Layer w0.305: U3.15 65.725,74.65 66.15,75.075 R12.2@66.45,75.075
NetN4_2: N4.2 P9.1 | length 65.3
  Bottom Layer w0.508: N4.2 98.112,73.712 110.4,86 P9.1@148.047,86
NetN4_3: N4.3 R13.2 U3.13 | length 24.7
  Top Layer w0.254: U3.13 68.925,73.35 R13.2 81.125,73.375 83.328,71.172 N4.3
NetN4_4: N4.4 U3.10 | length 24.9
  Top Layer w0.254: U3.10 64.1,71.375 67.889,71.375 70.632,68.632 v1(72.132,68.632)
  Bottom Layer w0.254: v1(72.132,68.632) N4.4
NetN4_9: N4.9 R44.2 | length 61.7
  Top Layer w0.508: R44.2 v1(65.7,20.925)
  Bottom Layer w0.508: v1(65.7,20.925) 67.3,22.525 67.3,26.2 72.1,31 83.6,31 94.2,41.6 94.2,54.7 92.968,55.932 N4.9
NetN4_10: N4.10 R43.2 | length 50.4
  Top Layer w0.508: R43.2 v1(65.7,26.625)
  Bottom Layer w0.508: v1(65.7,26.625) 71.075,32 82.2,32 92.2,42 92.2,52.2 91.032,53.368 N4.10
NetN4_11: N4.11 R33.2 | length 35.8
  Top Layer w0.254: R33.2 R33.2@56.601,60.051
  Top Layer w0.508: R33.2 56.35,59.6 v1(75.1,59.6)
  Bottom Layer w0.508: v1(75.1,59.6) 77.4,59.6 86.151,50.849 N4.11
NetN4_12: N4.12 R35.2 | length 34
  Top Layer w0.508: R35.2 v1(75.1,54)
  Bottom Layer w0.508: v1(75.1,54) 78.7,54 84.412,48.288 N4.12
NetN4_13: N4.13 U1.3 U2.3 | length 142.5
  Top Layer w0.254: U2.3 5.974,14.874 5.3,14.2 5.3,7.8 5.5,7.6 21.851,7.6 ; U1.3 23.477,12.577 22,11.1 22,7.749 21.851,7.6 ; v1(83.5,35.1) 80.5,32.1 72.2,32.1 67.8,27.7 67.8,7.6 65.1,4.9 24.551,4.9 21.851,7.6
  Bottom Layer w0.254: v1(83.5,35.1) 90,41.6 90,44.9 89.128,45.772 N4.13
NetN4_17: N4.17 R16.1 | length 6.8
  Top Layer w0.305: R16.1@114.872,71.172 R16.1
  Top Layer w0.508: N4.17 R16.1@114.872,71.172
NetN4_20: N4.20 U10.3 | length 75
  Top Layer w0.254: U10.3 56.4,89 59.6,85.8 94.8,85.8 105.5,75.1 105.5,66.242 N4.20
NetN4_21: N4.21 P10.1 P11.1 | length 10.5
  Top Layer w0.508: N4.21 P11.1@115.508,61.012 ; P11.1@115.258,61.012 P11.1 115.373,60.811 P10.1
NetN4_27: N4.27 R10.1 | length 45.8
  Top Layer w0.254: v1(70.5,34.6) 75.6,34.6 79.75,38.75 91,38.75 98,45.75 108.168,45.75 N4.27
  Top Layer w0.508: R10.1 69.1,36 v1(70.5,34.6)
NetP2_1: P2.1 U7.1 U7.4 | length 19.1
  Top Layer w0.508: P2.1 24.5,86 25,85.5 25,83.852 ; U7.1 24.702,84.15 25,83.852 ; U7.4 25.298,82.25 25,82.548 25,83.852
NetP3_1: P3.1 U8.1 U8.4 | length 26
  Top Layer w0.508: P3.1 17.5,66 18,66.5 18,71.202 18.298,71.5 27.202,71.5 27.5,71.202 27.5,69.902 ; U8.1 27.202,70.2 27.5,69.902 ; U8.4 28.2,68.3 27.5,69 27.5,69.902
NetP6_1: P6.1 P6.8 R23.1 | length 18.1
  Top Layer w0.508: R23.1 72.75,5.9 74.5,5.9 76.895,8.295 ; P6.1 76.895,8.295 ; P6.8 77.098,15.995 76.8,15.697 76.8,8.39 76.895,8.295
NetP7_6: P7.6 R21.1 | length 16.1
  Top Layer w0.508: R21.1 84.3,24.9 85.7,26.3 96.532,26.3 96.83,26.002 P7.6
NetP7_8: P7.8 R20.1 | length 18.8
  Top Layer w0.508: R20.1 98.9,27.1 99.37,26.63 P7.8
NetP7_10: P7.10 U11.5 | length 64.1
  Top Layer w0.305: U11.5 142.388,56.512 v1(142.4,56.5)
  Bottom Layer w0.508: P7.10 104.02,26.6 113.4,26.6 126,39.2 126,53.2 129.3,56.5 v1(142.4,56.5)
NetP7_12: P7.12 U12.5 | length 31.1
  Top Layer w0.254: v1(112.3,4.1) 112.305,4.095 113.941,4.095 114.239,4.392 U12.5
  Bottom Layer w0.508: P7.12 110.762,24.49 111.06,24.192 111.06,7.452 111.007,7.399 111.007,6.558 111.06,6.505 111.06,5.34 v1(112.3,4.1)
NetP10_2: P10.2 R39.2 U9.2 | length 6.2
  Top Layer w0.508: P10.2 117.973,58.067 R39.2 118.273,55.977 118.569,55.681 118.569,55.381 119.393,54.557 U9.2
NetP11_2: P11.2 R47.2 U16.1 | length 4.8
  Top Layer w0.508: P11.2@117.963,61.177 120.573,61.177 U16.1
NetR2_2: R2.2 R3.1 U15.4 | length 6.1
  Top Layer w0.432: R3.1 36.9,46.25 U15.4 40.75,46.265 R2.2
NetR6_1: R6.1 U1.5 | length 4.6
  Top Layer w0.254: U1.5 29.972,11.577 29.823,11.428 29.823,9.377 30.023,9.177 R6.1
NetR7_1: R7.1 U2.6 | length 2.9
  Top Layer w0.305: U2.6 8.882,12.924 8.819,12.861 8.819,11.912 8.998,11.734 9.352,11.734 9.75,11.336 R7.1
NetR14_1: R14.1 U3.9 | length 2.4
  Top Layer w0.305: U3.9 65.975,70.75 R14.1
NetR15_1: R15.1 U3.16 | length 1.3
  Top Layer w0.305: U3.16 64.127,75.3 64.15,75.323 R15.1
NetR25_2: R25.2 U4.3 | length 2.3
  Top Layer w0.305: R25.2 R25.2@131.115,22.015
  Top Layer w0.508: R25.2@131.115,22.015 U4.3
NetR26_2: R26.2 U4.7 | length 2.6
  Top Layer w0.305: R26.2@140.915,23.285 R26.2
  Top Layer w0.508: U4.7 R26.2@140.915,23.285
NetR28_2: R28.2 U5.3 | length 2.2
  Top Layer w0.508: R28.2@131.15,33.6 131.235,33.515 U5.3
NetR29_2: R29.2 U5.7 | length 2.5
  Top Layer w0.508: U5.7 R29.2@141.15,34.785
NetR31_2: R31.2 U6.3 | length 2.4
  Top Layer w0.508: R31.2@130.9,45.7 130.985,45.615 U6.3
NetR32_2: R32.2 U6.7 | length 2.9
  Top Layer w0.508: U6.7 140.954,46.885 141.25,46.589 R32.2@141.25,46.45
NetR33_1: R33.1 R38.1 U13.2 | length 3.7
  Top Layer w0.254: R38.1 R33.1 53.5,59.65 U13.2
NetR34_1: R34.1 U3.3 | length 36
  Top Layer w0.508: R34.1 26.55,76.798 26.848,76.5 53.425,76.5 53.45,76.525 55.975,74 U3.3
NetR35_1: R35.1 R36.1 U13.5 | length 3.6
  Top Layer w0.254: R36.1 R35.1 53.5,54.05 U13.5
NetR37_1: R37.1 U3.7 | length 36.2
  Top Layer w0.508: R37.1 28.974,64.298 29.271,64 36,64 39,67 39,70.5 39.875,71.375 58.4,71.375 U3.7
NetR41_1: R41.1 U10.5 | length 4.6
  Top Layer w0.254: U10.5 50.101,90 50.249,90.149 50.249,92.051 50.101,92.2 R41.1@48.999,92.2
NetR43_1: R43.1 R46.1 U14.2 | length 3.8
  Top Layer w0.254: R46.1 R43.1 60.4,26.575 U14.2
NetR44_1: R44.1 R45.1 U14.5 | length 3.7
  Top Layer w0.254: R45.1 R44.1 60.4,20.975 U14.5
pos_out: C4.2 C5.2 C6.2 C37.2 C38.2 C39.2 C40.2 C46.1 C48.2 N1.4 pad.16@43,12 U1.9 U1.10 U7.2 U8.2 U15.2 | length 39
  Top Layer w0.254: U1.9 37.273,13.077 C48.2@37.723,13.527 ; U1.10 C48.2@37.723,13.577 ; C48.2@37.723,13.677 C48.2@37.973,13.677
  Top Layer w0.508: v1(17.4,84.348) 17.402,84.35 C39.2 C40.2 21.7,83.498 21.998,83.2 U7.2 ; v1(19.924,70.398) 19.926,70.4 C38.2 C37.2 24.124,69.548 24.421,69.25 U8.2 ; C6.2 v1(38.123,15.477) 38.123,13.827 C48.2@37.973,13.677 ; C4.2@36.71,33.74 N1.4 39.26,36.09 C46.1@39.35,36 ; C4.2 36.75,31.998 37.048,31.7 v1(40.5,31.7) ; U15.2 45.75,45.3 C5.2 45.819,45.269 47.669,45.269 v1(47.7,45.3)
REFCAP: C10.2 N3.6 | length 2
  Top Layer w0.305: C10.2@59.4,41.15 59.475,41.225 N3.6
REFIO: C11.2 C12.2 N3.4 N3.15 | length 10.7
  Top Layer w0.305: N3.4 63.325,42.525 64.625,43.825 N3.15 69.3,43.825 71.475,43.825 C12.2@71.5,43.85
SPI1_CS_SRAM1: N4.26 R24.2 U4.1 | length 39.2
  Top Layer w0.508: N4.26 123.9,32.602 123.9,25.6 124.9,24.6 R24.2 131.145,24.555 U4.1
SPI1_CS_SRAM2: N4.25 R27.2 U5.1 | length 31.2
  Top Layer w0.508: N4.25 123.055,36 R27.2 131.205,36.055 U5.1
SPI1_CS_SRAM3: N4.24 R30.2 U6.1 | length 27.2
  Top Layer w0.508: N4.24 113.517,48.1 R30.2 131.055,48.155 U6.1
SPI1_MISO: N3.13 N4.8 U3.8 | length 71.8
  Top Layer w0.254: U3.8 60.101,70.75 60.25,70.601 60.25,65.325 60.75,64.825 79.925,64.825 85,59.75 85,58.4 ; N3.13 84.525,42.525 85,43 85,58.4 ; N4.8 85.072,58.472 85,58.4
SPI1_MOSI: N3.10 N4.22 U3.14 | length 101.4
  Top Layer w0.254: U3.14 67.525,74 68.025,74.5 81.5,74.5 83.5,72.5 93.5,72.5 99,67 99,58.472 ; N3.10 68.225,40.575 68.6,40.2 90.95,40.2 99,48.25 99,58.472 ; N4.22 99,58.472
SPI1_SCK: N3.12 N4.7 U3.12 | length 73.5
  Top Layer w0.254: U3.12 66.475,72.7 66.675,72.5 76.382,72.5 N4.7 87.882,61 90,61 91,60 91,42.9 90.154,42.054 68.945,42.054 68.766,41.875 N3.12
SPI1_SRAM_MISO: P6.7 P7.9 R17.2 U4.2 U5.2 U6.2 | length 90.8
  Top Layer w0.508: P6.7 89.306,14.895 90.211,15.8 94.8,15.8 95.8,16.8 R17.2@95.8,18.7 ; R17.2 95.6,18.95 95.6,22.602 96.298,23.3 102,23.3 ; P7.9 101.91,23.21 102,23.3 ; U6.2 134.702,46.885 135,46.587 135,34.8 ; U5.2 134.985,34.785 135,34.8 ; 102,23.3 133.413,23.3 U4.2 133.443,23.3 134.702,23.3 135,23.598 135,34.8
SPI1_SRAM_MOSI: P6.3 P7.7 R18.2 U4.5 U5.5 U6.5 | length 99
  Top Layer w0.508: P6.3 83.005,10.495 83.55,9.95 97.25,9.95 101.1,13.8 v1(101.1,17.5) 101.1,20.22 P7.7 ; v1(109.1,16.8) 132.71,16.8 136.655,20.745 ; U6.5 137.498,44.345 136.6,43.447 136.6,32.3 ; U5.5 136.655,32.245 136.6,32.3 ; U4.5 136.655,20.745 ; 136.6,32.3 136.6,20.8 136.655,20.745
  Bottom Layer w0.508: v1(101.1,17.5) 101.8,16.8 v1(109.1,16.8)
SPI1_SRAM_SCK: P6.5 P7.5 U4.6 U5.6 U6.6 | length 111.1
  Top Layer w0.508: P6.5 96.502,12.695 98.3,14.493 v1(98.3,19.3) 98.3,20.606 P7.5@97.08,21.826 ; P7.5 96.956,21.95 P7.5@97.08,21.826 ; P7.5@97.08,22 P7.5@97.08,21.826 ; v1(108.8,15) 139.3,15 141.2,16.9 v1(141.2,20.8) 140.01,21.99 138.797,21.99 U4.6 ; U6.6 139.743,45.615 v1(141.168,44.19) ; U5.6 138.647,33.49 139.91,33.49 v1(141.2,32.2)
  Bottom Layer w0.508: v1(98.3,19.3) 98.3,17.4 100.7,15 v1(108.8,15) ; v1(141.168,44.19) 141.2,44.158 v1(141.2,32.2) v1(141.2,20.8) v1@141.3,20.7
SPI2_NSS: P6.2 P7.11 R19.2 | length 34.4
  Top Layer w0.508: P6.2 81.805,9.395 82.35,8.85 R19.2 97.85,8.85 104.45,15.45 P7.11
TIA_out: K1.9 N1.6 R3.2 | length 19.2
  Top Layer w0.762: K1.9 26.454,47.08 26.9,46.634 26.9,42.246 27.346,41.8 33.7,41.8 34.17,42.27 N1.6 34.17,46.28 R3.2
pads on no net: K1.3 K1.4 K1.5 K2.3 K2.4 K2.5 K2.8 N1.1 N1.5 N1.8 N4.5 N4.14 N4.15 N4.16 N4.19 N4.23 P6.G1 P6.G2 P6.G3 P6.G4 U1.4 U2.4 U2.7 U3.2 U3.6 U10.4 U11.3 U11.7 U12.3 U12.7 U16.2

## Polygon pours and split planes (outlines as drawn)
GND on Top inner "NONET_L-01_P-001" (solid, pour order 0): 0,100 160,100 160,0 0,0
pos_out on Bottom inner "POS_OUT_L03_P002" (solid, pour order 2): 22,17 23,17 31,17 32,16 32,0 50,0 50,49 48,51 48,61 46,63 43,63 41,65 41,82 40,83 35,83 33.996,81.996 26.004,81.996 21,87 16,87 15,86 15,78 16,77 35,77 37,75 37,70 36,69 29,69 26,72 19,72 17,70 17,52 19,50 38,50 40,48 40,35 39,34 37,34 36,33 36,30 34,28 24,28 22,26
DVDD_SD on Bottom inner "DVDD_SD_L03_P008" (solid, pour order 8): 107,20 109,18 109,0 70,0 70,18 72,20 107,20
DVDD on Bottom inner "DVDD_L03_P007" (solid, pour order 7): 109,0 128.5,0 160,0 160,100 64,100 64,42 63,41 50.137,41 50.137,0.137 50,0 70,0 70,18 72,20 107,20 109,18
NetC47_2 on Bottom inner "NETC47_2_L03_P006" (solid, pour order 6): 32,0 32,16 31,17 22,17 22,13 21,12 15,12 11.5,12 10.75,11.25 10.75,0
NetC49_2 on Bottom inner "NETC49_2_L03_P005" (solid, pour order 5): 11.5,12 10.75,11.25 10.75,0 0,0 0,16 13,16 14,15 14,12
AVDD on Bottom inner "AVDD_L03_P004" (solid, pour order 4): 35,100 35,83 40,83 41,82 41,65 43,63 46,63 48,61 48,51 50,49 50,41 63,41 64,42 64,100
neg_out on Bottom inner "NEG_OUT_L03_P001" (solid, pour order 1): 22,13 21,12 14,12 14,15 13,16 0,16 0,100 35,100 35,83 33.996,81.996 26.004,81.996 21,87 16,87 15,86 15,78 16,77 35,77 37,75 37,70 36,69 29,69 26,72 19,72 17,70 17,52 19,50 38,50 40,48 40,35 39,34 37,34 36,33 36,30 34,28 24,28 22,26
no net on Top Solder (solid): 160,100 0,100 0,97 160,97
no net on Top Solder "NONET_L04_P-001" (solid): 84.2,19.1 84.2,17.65 86.2,17.65 86.2,19.1
no net on Top Solder "NONET_L04_P-001" (solid): 75.9,19.1 75.9,17.65 77.9,17.65 77.9,19.1
no net on Top Solder "NONET_L04_P-001" (solid): 84.2,5.35 84.2,3.9 86.2,3.9 86.2,5.35
no net on Top Solder "NONET_L04_P-001" (solid): 75.9,5.35 77.9,5.35 77.9,3.9 75.9,3.9
GND on Top Layer "GND_L01_P012" (solid, pour order 12): 0,100 0,97 160,97 160,100
GND on Top Layer "GND_L01_P011" (solid, pour order 11): 0,3 0,0 160,0 160,3
GND on Bottom Layer "GND_L04_P014" (solid, pour order 14): 160,3 160,0 0,0 0,3
GND on Bottom Layer "GND_L04_P013" (solid, pour order 13): 0,100 0,97 160,97 160,100

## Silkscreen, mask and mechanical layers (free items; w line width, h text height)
Top Overlay:
  drawing of 9 lines, arcs and shapes, not listed
  text "gnd" at 48.039,74.203 h1.52 r90
  text "AVDD" at 44.297,72.703 h1.52 r90
  text "gnd" at 141.953,68.461 h1.52
  text "DVDD" at 141.953,64.203 h1.52
  text "gnd" at 3.703,22.461 h1.52
  text "neg" at 3.703,18.711 h1.52
  text "DVSD" at 65.453,16.203 h1.52
  text "gnd" at 44.703,15.461 h1.52
  text "gnd" at 66.953,12.461 h1.52
  text "pos" at 44.703,11.711 h1.52
Top Solder:
  rectangle: 0,0 160,3
Bottom Solder:
  rectangle: -0.254,97 159.746,100
  rectangle: 0,0 160,3
Mechanical 1:
  lines w0.254: 160,0 160,100 0,100 0,0 160,0 ; 160,0 160,0
Drill Drawing:
  circle w0.203: c2.726,122.297 r0.847
  lines w0.203: 1.88,113.83 2.726,114.253 3.573,113.83 3.15,114.677 3.573,115.523 2.726,115.1 1.88,115.523 2.303,114.677 1.88,113.83 ; 1.88,118.063 2.303,118.063 2.726,117.64 3.15,118.063 3.573,118.063 3.15,118.487 3.573,118.91 3.15,118.91 2.726,119.333 2.303,118.91 1.88,118.91 2.303,118.487 1.88,118.063 ; 1.88,126.953 3.573,126.953 2.726,125.26 1.88,126.953 ; 1.88,129.493 2.303,129.493 2.303,129.07 3.15,129.07 3.15,129.493 3.573,129.493 3.573,130.34 3.15,130.34 3.15,130.763 2.303,130.763 2.303,130.34 1.88,130.34 1.88,129.493 ; 1.88,132.88 1.88,133.303 2.303,133.727 1.88,134.15 1.88,134.573 2.303,134.573 2.726,134.15 3.15,134.573 3.573,134.573 3.573,134.15 3.15,133.727 3.573,133.303 3.573,132.88 3.15,132.88 2.726,133.303 2.303,132.88 1.88,132.88
  lines w0.254: 0.377,112.687 142.538,112.687 ; 0.377,135.547 142.538,135.547 ; 14.207,108.877 14.207,139.357 ; 29.087,108.877 29.087,139.357 ; 57.425,108.877 57.425,139.357 ; 70.112,108.877 70.112,139.357 ; 88.588,108.877 88.588,139.357 ; 126.575,108.877 126.575,139.357 ; 0.377,108.877 142.538,108.877 142.538,139.357 0.377,139.357 0.377,108.877
  text "Symbol" at 2.663,136.69 h1.83
  text "Count" at 15.35,136.69 h1.83
  text "Hole Size" at 30.23,136.69 h1.83
  text "Plated" at 58.568,136.69 h1.83
  text "Hole Type" at 71.255,136.69 h1.83
  text "Drill Layer Pair" at 89.731,136.69 h1.83
  text "Via/Pad" at 127.718,136.69 h1.83
  text "103" at 15.35,132.88 h1.52
  text "27,56mil (0,700mm)" at 30.23,132.88 h1.52
  text "PTH" at 58.568,132.88 h1.52
  text "Round" at 71.255,132.88 h1.52
  text "Top Layer - Bottom Layer" at 89.731,132.88 h1.52
  text "Via" at 127.718,132.88 h1.52
  text "7" at 15.35,129.07 h1.52
  text "31,50mil (0,800mm)" at 30.23,129.07 h1.52
  text "PTH" at 58.568,129.07 h1.52
  text "Round" at 71.255,129.07 h1.52
  text "Top Layer - Bottom Layer" at 89.731,129.07 h1.52
  text "Pad" at 127.718,129.07 h1.52
  text "6" at 15.35,125.26 h1.52
  text "31,50mil (0,800mm)" at 30.23,125.26 h1.52
  text "PTH" at 58.568,125.26 h1.52
  text "Round" at 71.255,125.26 h1.52
  text "Top Layer - Bottom Layer" at 89.731,125.26 h1.52
  text "Via" at 127.718,125.26 h1.52
  text "42" at 15.35,121.45 h1.52
  text "35,43mil (0,900mm)" at 30.23,121.45 h1.52
  text "PTH" at 58.568,121.45 h1.52
  text "Round" at 71.255,121.45 h1.52
  text "Top Layer - Bottom Layer" at 89.731,121.45 h1.52
  text "Pad" at 127.718,121.45 h1.52
  text "28" at 15.35,117.64 h1.52
  text "39,37mil (1,000mm)" at 30.23,117.64 h1.52
  text "PTH" at 58.568,117.64 h1.52
  text "Round" at 71.255,117.64 h1.52
  text "Top Layer - Bottom Layer" at 89.731,117.64 h1.52
  text "Pad" at 127.718,117.64 h1.52
  text "8" at 15.35,113.83 h1.52
  text "78,74mil (2,000mm)" at 30.23,113.83 h1.52
  text "PTH" at 58.568,113.83 h1.52
  text "Round" at 71.255,113.83 h1.52
  text "Top Layer - Bottom Layer" at 89.731,113.83 h1.52
  text "Pad" at 127.718,113.83 h1.52
  text "194 Total" at 15.35,110.02 h1.52

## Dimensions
0,100 to 0,97 on Mechanical 1
0,0 to 0,3 on Mechanical 1
0,0 to 160,0 on Mechanical 1
0,0 to 0,100 on Mechanical 1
